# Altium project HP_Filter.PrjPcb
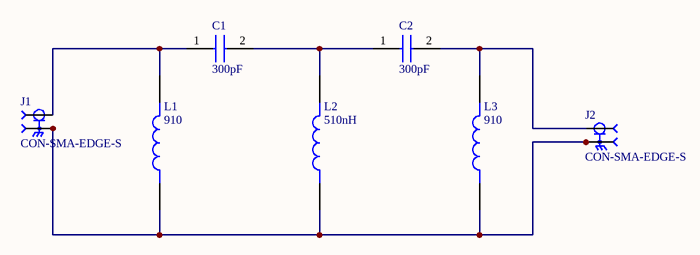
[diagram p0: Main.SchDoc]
1 sheet, 7 parts. Net scope: global (net labels, ports and power ports of the same name join across sheets).
Board file: HP_Filter.PcbDoc

## Sheet Main.SchDoc
size A; SheetNumber: 1; SheetTotal: 1

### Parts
C1  300pF  [CAPC1514X145N]
C2  300pF  [CAPC1514X145N]
J1  CON-SMA-EDGE-S  [RFSOLUTIONS_CON-SMA-EDGE-S]
J2  CON-SMA-EDGE-S  [RFSOLUTIONS_CON-SMA-EDGE-S]
L1  910  [IND_AISC-1008-R12G-T]
L2  510nH  [IND_AISC-1008-R12G-T]
L3  910  [IND_AISC-1008-R12G-T]

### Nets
NetC1_1: C1.1 J1.1 L1.2
NetC1_2: C1.2 C2.1 L2.2
NetC2_2: C2.2 J2.1 L3.2
NetJ1_G1: J1.G1 J1.G2 J1.G3 J1.G4 J2.G1 J2.G2 J2.G3 J2.G4 L1.1 L2.1 L3.1

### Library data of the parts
C1 C2 = 700A301KT150XTV: Capacitor; Manufacturer_Name: Kyocera AVX
J1 J2 = CON-SMA-EDGE-S: MF: {'manufacturer': u'RF Solutions'}
L1 L3 = AISC-1008-R12G-T: 120 nH Unshielded Drum Core, Wirewound Inductor 650 mA 630mOhm Max 1008 (2520 Metric); Partnumber: AISC-1008-R91G-T; MF: Abracon
L2 = AISC-1008-R12G-T: 120 nH Unshielded Drum Core, Wirewound Inductor 650 mA 630mOhm Max 1008 (2520 Metric); MF: Abracon; MP: AISC-Q0805-R51G-T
